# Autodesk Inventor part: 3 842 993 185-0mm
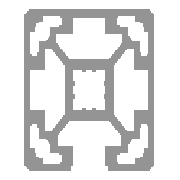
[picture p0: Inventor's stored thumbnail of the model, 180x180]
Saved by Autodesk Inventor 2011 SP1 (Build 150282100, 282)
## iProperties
Category: End -/-
Created: 2011-02
Part Number: 3 842 993 185-0mm
Document SubType Name: Modeling
Designer: SRW
Density: 2.71 g/cm^3
Categories: <MemberInstance><Categories><Category DisplayName="Structural Shapes" InternalName="089c4875-fa83-4c05-b084-43b9cc11f5ed" Mnemonic="GRDR"><CategoryParameter Dis
Stock Number: 3 842 993 185
Description: PROFILE 40x40 1S, -/-
Material: Aluminum-6061
Mass: 41.8201 g
Surface Area: 152.921 cm^2
Volume: 15.4318 cm^3
G_L: 25.000 mm
Author: SRW
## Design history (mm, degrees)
node "Blocks"
  sketch "40x40 1S"
    geometry: L1 (32.168, 29.304)-(31.901, 28.69); L2 (27.915, 28.69)-(27.648, 29.304); L3 (27.648, 29.304)-(24.708, 29.304); L4 (24.708, 29.304)-(24.708, 26.364); L5 (24.708, 26.364)-(25.323, 26.097); L6 (25.323, 22.111)-(24.708, 21.844); L7 (24.708, 21.844)-(24.708, 18.904); L8 (24.708, 18.904)-(27.648, 18.904); L9 (27.648, 18.904)-(27.915, 19.519); L10 (31.901, 19.519)-(32.168, 18.904); L11 (32.168, 18.904)-(35.108, 18.904); L12 (35.108, 18.904)-(35.108, 21.844); L13 (44.408, 35.854)-(45.408, 35.854); L14 (45.408, 35.854)-(45.408, 33.604); L15 (48.408, 33.604)-(48.408, 38.604); L16 (48.408, 38.604)-(47.158, 38.604); L17 (44.408, 41.354)-(44.408, 42.604); L18 (44.408, 42.604)-(39.408, 42.604); L19 (39.408, 39.604)-(41.658, 39.604); L20 (41.658, 39.604)-(41.658, 38.604); L21 (34.908, 38.104)-(34.908, 42.104); L22 (34.908, 42.104)-(24.908, 42.104); L23 (24.908, 42.104)-(24.908, 38.104); L24 (24.908, 38.104)-(19.658, 38.104); L25 (19.658, 35.768)-(23.822, 31.604); L26 (23.822, 31.604)-(35.994, 31.604); L27 (35.994, 31.604)-(40.158, 35.768); L28 (40.158, 35.768)-(40.158, 38.104); L29 (40.158, 38.104)-(34.908, 38.104); L30 (15.908, 19.104)-(15.908, 13.854); L31 (15.908, 13.854)-(18.244, 13.854); L32 (18.244, 13.854)-(22.408, 18.018); L33 (22.408, 18.018)-(22.408, 30.19); L34 (22.408, 30.19)-(18.244, 34.354); L35 (18.244, 34.354)-(15.908, 34.354); L36 (15.908, 34.354)-(15.908, 29.104); L37 (15.908, 29.104)-(11.408, 29.104); L38 (11.408, 29.104)-(11.408, 19.104); L39 (11.408, 19.104)-(15.908, 19.104); L40 (15.408, 12.354)-(14.408, 12.354); L41 (14.408, 12.354)-(14.408, 14.604); L42 (11.408, 14.604)-(11.408, 9.604); L43 (11.408, 9.604)-(12.658, 9.604); L44 (15.408, 6.854)-(15.408, 5.604); L45 (15.408, 5.604)-(20.408, 5.604); L46 (20.408, 8.604)-(18.158, 8.604); L47 (18.158, 8.604)-(18.158, 9.604); L48 (18.158, 38.604)-(18.158, 39.604); L49 (18.158, 39.604)-(20.408, 39.604); L50 (20.408, 42.604)-(15.408, 42.604); L51 (15.408, 42.604)-(15.408, 41.354); L52 (12.658, 38.604)-(11.408, 38.604); L53 (11.408, 38.604)-(11.408, 33.604); L54 (14.408, 33.604)-(14.408, 35.854); L55 (14.408, 35.854)-(15.408, 35.854); L56 (19.658, 38.104)-(19.658, 35.768); L57 (46.908, 44.104)-(12.908, 44.104); L58 (9.908, 41.104)-(9.908, 7.104); L59 (12.908, 4.104)-(24.108, 4.104); L60 (24.108, 4.104)-(24.108, 5.604); L61 (24.108, 5.604)-(24.908, 5.604); L62 (24.908, 5.604)-(24.908, 10.104); L63 (24.908, 10.104)-(19.858, 10.104); L64 (19.858, 10.104)-(19.858, 12.64)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; A1 r 5 centre (29.908, 24.104) between (31.901, 28.69) and (27.915, 28.69); A2 r 5 centre (29.908, 24.104) between (25.323, 26.097) and (25.323, 22.111); A3 r 5 centre (29.908, 24.104) between (27.915, 19.519) and (31.901, 19.519); A4 r 1.5 centre (46.908, 33.604) between (45.408, 33.604) and (48.408, 33.604); A5 r 2.75 centre (44.408, 38.604) between (47.158, 38.604) and (44.408, 41.354); A6 r 1.5 centre (39.408, 41.104) between (39.408, 42.604) and (39.408, 39.604); A7 r 2.75 centre (44.408, 38.604) between (41.658, 38.604) and (44.408, 35.854); A8 r 1.5 centre (12.908, 14.604) between (14.408, 14.604) and (11.408, 14.604); A9 r 2.75 centre (15.408, 9.604) between (12.658, 9.604) and (15.408, 6.854); A10 r 1.5 centre (20.408, 7.104) between (20.408, 5.604) and (20.408, 8.604); A11 r 2.75 centre (15.408, 9.604) between (18.158, 9.604) and (15.408, 12.354); A12 r 1.5 centre (20.408, 41.104) between (20.408, 39.604) and (20.408, 42.604); A13 r 2.75 centre (15.408, 38.604) between (15.408, 41.354) and (12.658, 38.604); A14 r 1.5 centre (12.908, 33.604) between (11.408, 33.604) and (14.408, 33.604); A15 r 2.75 centre (15.408, 38.604) between (15.408, 35.854) and (18.158, 38.604); A16 r 3 centre (12.908, 41.104) between (12.908, 44.104) and (9.908, 41.104); A17 r 3 centre (12.908, 7.104) between (9.908, 7.104) and (12.908, 4.104); A18 r 3 centre (46.908, 7.104) between (46.908, 4.104) and (49.908, 7.104); A19 r 3 centre (46.908, 41.104) between (49.908, 41.104) and (46.908, 44.104); A20 r 1.5 centre (39.408, 7.104) between (39.408, 8.604) and (39.408, 5.604); A21 r 2.75 centre (44.408, 9.604) between (44.408, 6.854) and (47.158, 9.604); A22 r 1.5 centre (46.908, 14.604) between (48.408, 14.604) and (45.408, 14.604); A23 r 2.75 centre (44.408, 9.604) between (44.408, 12.354) and (41.658, 9.604); A24 r 5 centre (29.908, 24.104) between (34.494, 22.111) and (34.494, 26.097); 1 further point
    constraints: 192 end point, 48 point on circle, 24 centre point, 1 coincident
node "Start Plane"
node "End Plane"
sketch "Sketch1"
  geometry: 1 further point
  constraints: 1 other
extrude "Body" new body sketch "Sketch1" stored distance "d4" = 0.13; taper "d5" = 0 deg
node "Driven Length"
  sketch "Sketch49"
    geometry: L1 (0, 0)-(10, 0) reference
    constraints: 2 end point, 1 horizontal
  workplane "Work Plane21"
  sketch "Sketch50"
    geometry: L1 (-28, 0)-(28, 0) reference; L2 (-28, 25)-(28, 25) reference
    dimensions: "d7" = 25 distance between parallel lines of L1 L2 (derived)
sketch "Sketch9"
  geometry: 1 further point
hole "M12/-" sketch "Sketch9" at (0, 0) diameter "d17" = 10.106; stored, may be unused: countersink angle "d21" = 90 deg, drill point angle "d23" = 118 deg; dims "d18" = 6, "d19" = 4, "d20" = 2, "d22" = 55
sketch "Sketch10"
  geometry: 1 further point
hole "-/M12" sketch "Sketch10" at (0, 0) diameter "d24" = 10.106; stored, may be unused: countersink angle "d28" = 90 deg, drill point angle "d30" = 118 deg; dims "d25" = 6, "d26" = 4, "d27" = 2, "d29" = 55
sketch "Sketch11"
  geometry: L1 (-13.7, 0)-(12.2, 0) reference; C1 r 8.5 at (0, 20); 1 further point
  constraints: 1 centre point, 1 vertical alignment
  dimensions: "d31" = 20 distance from line of C1.centre L1; "d32" = 17 diameter of C1
extrude "D17/-" cut sketch "Sketch11" stored distance "d33" = 10; taper "d34" = 0 deg
sketch "Sketch12"
  geometry: L1 (-13.7, 25)-(12.2, 25) reference; C1 r 8.5 at (0, 5); 1 further point
  constraints: 1 centre point, 1 vertical alignment
  dimensions: "d35" = 17 diameter of C1; "d36" = 20 distance from line of L1 C1.centre
extrude "-/D17" cut sketch "Sketch12" stored distance "d37" = 10; taper "d38" = 0 deg
sketch "Sketch13"
  geometry: L1 (-12.98, 0)-(7.88, 0) reference; C1 r 4.9 at (0, 20); 1 further point
  constraints: 1 centre point, 1 vertical alignment
  dimensions: "d39" = 9.8 diameter of C1; "d40" = 20 distance from line of C1.centre L1
extrude "D9.8/-" cut sketch "Sketch13" stored distance "d41" = 10; taper "d42" = 0 deg
sketch "Sketch14"
  geometry: L1 (-12.98, 25)-(7.88, 25) reference; C1 r 4.9 at (0, 5); 1 further point
  constraints: 1 centre point, 1 vertical alignment
  dimensions: "d43" = 9.8 diameter of C1; "d44" = 20 distance from line of L1 C1.centre
extrude "-/D9.8" cut sketch "Sketch14" stored distance "d45" = 10; taper "d46" = 0 deg
sketch "Sketch15"
  geometry: L1 (-6.86, 25)-(6.86, 25) reference; C1 r 4.9 at (0, 5); 1 further point
  constraints: 1 centre point, 1 vertical alignment
  dimensions: "d47" = 9.8 diameter of C1; "d48" = 20 distance from line of L1 C1.centre
extrude "-/D9.8VS" cut sketch "Sketch15" stored distance "d49" = 10; taper "d50" = 0 deg
sketch "Sketch26"
  geometry: L1 (-6.86, 0)-(6.86, 0) reference; C1 r 4.9 at (0, 20); 1 further point
  constraints: 1 centre point, 1 vertical alignment
  dimensions: "d62" = 9.8 diameter of C1; "d65" = 20 distance from line of L1 C1.centre
extrude "D9.8VS/-" cut sketch "Sketch26" stored distance "d63" = 10; taper "d64" = 0 deg
sketch "Sketch37"
  geometry: L1 (-11.9, 0)-(11.9, 0) reference; L2 (-11.9, 25)-(11.9, 25) reference; C1 r 8.5 at (0, 20); 1 further point
  constraints: 1 centre point, 1 vertical alignment
  dimensions: "d76" = 20 distance from line of C1.centre L1; "d77" = 17 diameter of C1
extrude "D17VS/-" cut sketch "Sketch37" stored distance "d78" = 10; taper "d79" = 0 deg
sketch "Sketch38"
  geometry: L1 (-11.9, 25)-(11.9, 25) reference; C1 r 8.5 at (0, 5); 1 further point
  constraints: 1 centre point, 1 vertical alignment
  dimensions: "d80" = 17 diameter of C1; "d81" = 20 distance from line of L1 C1.centre
extrude "-/D17VS" cut sketch "Sketch38" stored distance "d82" = 10; taper "d83" = 0 deg
body "Solid1"
node "40x40 1S:1"
other parameters: "Length" = 25, "G_OFFSET_START" = 0 [user parameter; used in 2 equation terms], "G_OFFSET_END" = 0 [user parameter; used in 2 equation terms], "d2" = 0 (computed from G_OFFSET_START), "d3" = 25 (= Length + G_OFFSET_END), "G_L" = 25 (= d7) [user parameter], "Length2" = 25 (= G_OFFSET_START + Length + G_OFFSET_END) [user parameter], "d94" = 90 deg
